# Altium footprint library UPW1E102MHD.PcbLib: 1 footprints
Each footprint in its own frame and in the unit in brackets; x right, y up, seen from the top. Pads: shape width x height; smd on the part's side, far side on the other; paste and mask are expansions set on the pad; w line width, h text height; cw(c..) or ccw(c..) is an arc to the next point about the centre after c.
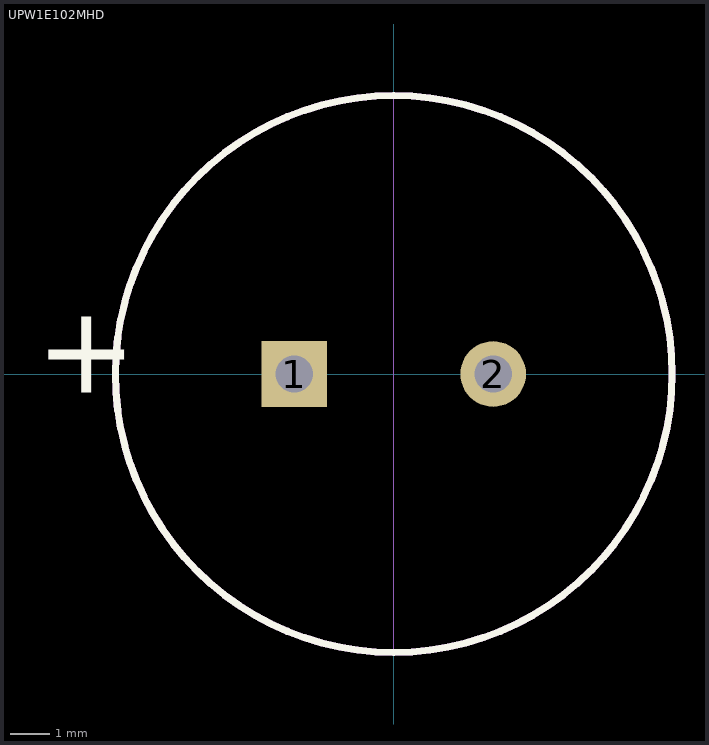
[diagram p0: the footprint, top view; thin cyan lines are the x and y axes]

## UPW1E102MHD [mil] "12.5Dx20T-5mmLS"
height 866.14
pads (2):
  rect 65x65 hole 37: 1(-98.43,0)
  round 65 hole 37: 2(98.43,0)
Top Overlay:
  circle w7: c0,0 r275.59
  text "+" at -354.33,-47.24 h150
M5 Assembly Top:
  circle w7: c0,0 r275.59
  text "+" at -354.33,-47.24 h150
  text ".Designator" at -165.35,-15.75 h72.83
M13 Component Bodies Top:
  lines w1: 0,-275.59 ccw(c0,0) 0,275.59 0,-275.59
3D body: height 866.14, standoff 0, extent -275.58,-275.58 275.6,275.6
3D body: height 870.08, standoff 866.14, extent -0.02,-275.61 275.61,275.61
